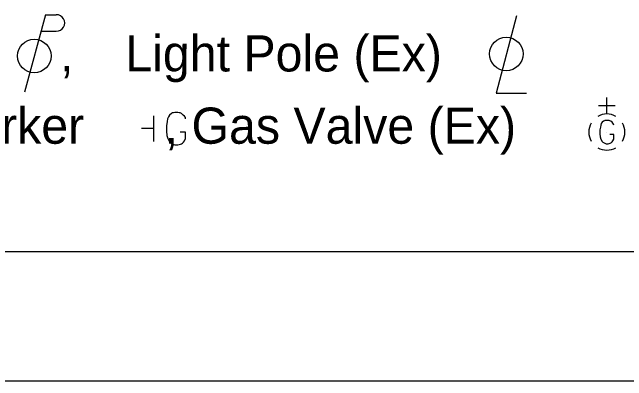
# Model space of a CAD drawing. Extents: x 0 to 34, y 0 to 22.
# Drawn here: x 11.769 to 14.152, y 0 to 1.428 of the extents above; entities that cross this region are included whole.
import ezdxf

# ---------------------------------------------------------------- set-up
doc = ezdxf.new("R2010")
doc.units = 0
for name, color, linetype in [('SH_Border', 7, 'Continuous'), ('SH_Cut_Line', 7, 'Continuous'), ('SH_Text', 7, 'Continuous'), ('UT_X_Gas_Cells', 7, 'Continuous')]:
    doc.layers.add(name, color=color, linetype=linetype)

msp = doc.modelspace()

# ---------------------------------------------------------------- linework, layer by layer
at = {"layer": 'SH_Border'}
msp.add_lwpolyline([(1.5, 21.5), (33.5, 21.5), (33.5, 0.5), (1.5, 0.5)], close=True, dxfattribs=at)
at = {"layer": 'SH_Cut_Line'}
msp.add_lwpolyline([(0, 0), (34, 0), (34, 22), (0, 22)], close=True, dxfattribs=at)
at = {"layer": 'SH_Text'}
for p, q in [((11.8976, 1.4185), (11.8172, 1.1185)), ((11.8976, 1.4185), (11.9401, 1.4185)), ((11.8805, 1.3547), (11.9401, 1.3547))]:
    msp.add_line(p, q, dxfattribs=at)
msp.add_lwpolyline([(13.7246, 1.4143), (13.6458, 1.115), (13.764, 1.115)], dxfattribs=at)
for centre in [(11.8547, 1.2585), (13.6852, 1.2666)]:
    msp.add_circle(centre, 0.065, dxfattribs=at)
msp.add_arc((11.9407, 1.3866), 0.0319, 268.8767, 91.1233, dxfattribs=at)
at = {"layer": 'UT_X_Gas_Cells'}
for p, q in [((14.0751, 1.0337), (14.0751, 1.0972)), ((14.107, 1.0654), (14.0433, 1.0654)), ((12.3177, 0.9271), (12.3177, 1.0271)), ((12.3177, 0.9771), (12.2701, 0.9771)), ((14.0751, 0.9637), (14.0751, 0.9637))]:
    msp.add_line(p, q, dxfattribs=at)
for points in [[(12.4415, 1.0149), (12.4405, 1.0199), (12.4376, 1.0248), (12.4326, 1.0297), (12.4257, 1.0356), (12.4208, 1.0376), (12.4169, 1.0386), (12.411, 1.0396), (12.3992, 1.0396), (12.3943, 1.0386), (12.3913, 1.0376), (12.3874, 1.0356), (12.3795, 1.0297), (12.3746, 1.0228), (12.3716, 1.0149), (12.3696, 1.0041), (12.3677, 0.9884), (12.3677, 0.9677), (12.3687, 0.951), (12.3726, 0.9382), (12.3785, 0.9264), (12.3834, 0.9224), (12.3893, 0.9185), (12.4002, 0.9146), (12.411, 0.9146), (12.4218, 0.9165), (12.4257, 0.9185), (12.4297, 0.9205), (12.4336, 0.9244), (12.4376, 0.9303), (12.4415, 0.9392), (12.4415, 0.9638), (12.4208, 0.9638)], [(14.1018, 0.991), (14.1011, 0.9945), (14.099, 0.998), (14.0954, 1.0016), (14.0904, 1.0058), (14.0869, 1.0073), (14.0841, 1.008), (14.0798, 1.0087), (14.0713, 1.0087), (14.0678, 1.008), (14.0656, 1.0073), (14.0628, 1.0058), (14.0571, 1.0016), (14.0536, 0.9966), (14.0515, 0.991), (14.0501, 0.9832), (14.0486, 0.9718), (14.0486, 0.9569), (14.0493, 0.9449), (14.0522, 0.9357), (14.0564, 0.9272), (14.06, 0.9243), (14.0642, 0.9215), (14.072, 0.9187), (14.0798, 0.9187), (14.0876, 0.9201), (14.0904, 0.9215), (14.0933, 0.9229), (14.0961, 0.9258), (14.099, 0.93), (14.1018, 0.9364), (14.1018, 0.9541), (14.0869, 0.9541)]]:
    msp.add_lwpolyline(points, dxfattribs=at)
for start, end in [(60.0184, 120.0157), (150.0184, 209.9816), (330.0184, 29.9816), (239.9843, 299.9816)]:
    msp.add_arc((14.0752, 0.9637), 0.07, start, end, dxfattribs=at)

# ---------------------------------------------------------------- texts
at = {"layer": 'SH_Text'}
for s, p in [('Telephone Pole (Ex)        , Power Pole (Ex)        , ', (7.9591, 1.1985)), ('Light Pole (Ex)     ', (12.2078, 1.1985)), ('Telephone Power Pole (Ex)      , Gas Line Marker      , Gas Valve (Ex)', (7.9591, 0.9185))]:
    msp.add_text(s, height=0.14, dxfattribs=at).set_placement(p)

doc.saveas('drawing.dxf')
